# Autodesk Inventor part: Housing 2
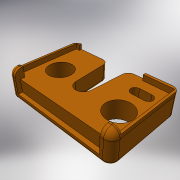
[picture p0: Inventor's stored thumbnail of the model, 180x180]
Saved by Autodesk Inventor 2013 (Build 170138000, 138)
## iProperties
Shininess: 64.0
Length Units: 11269
Angle Units: 11279
Time Units: 11290
Mass Units: 11283
Length Display Precision: 3
Angle Display Precision: 2
Compacted: True
Part Number: Housing 2
Document SubType Name: Modeling
Created: 2005-02
Material: ABS Plastic
Designer: =<Author>
Manufacturer: Standard
Standards Organization: Custom
Density: 1.06 g/cm^3
Description: =<Part Number>
Mass: 41.8001 g
Surface Area: 131.422 cm^2
Volume: 39.4341 cm^3
Density: 0.0
Volumn: 0.0
Area: 0.0
PropertySet Name: Model Information
Control State: 0
Master: False
Checked Out: False
Checked Out Date: 2008-10-15
Last Check In Date: 2008-10-15
d0: 53.000 mm
d1: 79.000 mm
d2: 20.000 mm
d3: 0.00 deg
d4: 2.000 mm
d5: 52.000 mm
d6: 5.000 mm
d11: 7.000 mm
d12: 6.000 mm
d13: 2.000 mm
d14: 2.000 mm
d15: 6.000 mm
d16: 7.000 mm
d17: 2.000 mm
d18: 2.000 mm
d19: 7.000 mm
d20: 0.00 deg
d21: 5.000 mm
d22: 3.000 mm
d23: 0.00 deg
d24: 13.000 mm
d25: 3.000 mm
d26: 0.00 deg
d28: 0.00 deg
d29: 15.000 mm
d30: 40.000 mm
d31: 7.000 mm
d32: 7.000 mm
d34: 0.00 deg
d35: 2.000 mm
d36: 5.000 mm
Author: PVitaliy
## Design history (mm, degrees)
sketch "Эскиз1"
  geometry: L1 (0, 0)-(79, 0); L2 (79, 0)-(79, 53); L3 (79, 53)-(0, 53); L4 (0, 53)-(0, 0)
  constraints: 8 end point, 2 parallel, 1 horizontal, 1 perpendicular, 1 other
  dimensions: "d0" = 53 distance of L3.end L1.start; "d1" = 79 distance of L1.start L1.end
extrude "Выдавливание1" new body sketch "Эскиз1" distance "d2" = 20; taper "d3" = 0 deg
sketch "Эскиз2"
  geometry: L1 (0, 0)-(0, 53) reference; L2 (79, 0)-(0, 0) reference; L3 (79, 53)-(79, 0) reference; L4 (0, 53)-(79, 53) reference; L5 (72, 2)-(7, 2); L6 (2, 6)-(2, 51); L7 (77, 51)-(77, 6); L8 (57, 51)-(57, 53); L9 (5, 51)-(5, 53); L10 (7, 2)-(7, 6); L11 (7, 6)-(2, 6); L12 (77, 6)-(72, 6); L13 (72, 6)-(72, 2); L14 (2, 51)-(5, 51); L15 (57, 51)-(77, 51)
  constraints: 22 end point, 3 perpendicular, 2 collinear, 2 parallel, 2 point on line
  dimensions: "d4" = 2 distance between parallel lines of L3 L7; "d5" = 52 distance between parallel lines of L9 L8; "d6" = 5 distance between parallel lines of L1 L9; "d11" = 7 distance between parallel lines of L10 L1; "d12" = 6 distance between parallel lines of L2 L11; "d13" = 2 distance between parallel lines of L1 L6; "d14" = 2 distance between parallel lines of L2 L5; "d15" = 6 distance between parallel lines of L2 L12; "d16" = 7 distance between parallel lines of L3 L13; "d18" = 2 distance between parallel lines of L15 L4
extrude "Выдавливание2" cut sketch "Эскиз2" distance "d19" = 7; taper "d20" = 0 deg
fillet "Сопряжение1" dims "d21" = 5
sketch "Эскиз3"
  geometry: L1 (57, 53)-(74, 53) reference; L2 (57, 53)-(57, 51) reference; L3 (57, 51)-(77, 51) reference; L4 (77, 51)-(77, 6) reference; L5 (72, 2)-(7, 2) reference; L6 (2, 6)-(2, 51) reference; L7 (2, 51)-(5, 51) reference; L8 (5, 51)-(5, 53) reference; L9 (0, 5)-(0, 48) reference; L10 (74, 0)-(5, 0) reference; L11 (79, 48)-(79, 5) reference; L12 (2, 6)-(0, 6); L13 (7, 2)-(7, 0); L14 (72, 2)-(72, 0); L15 (77, 6)-(79, 6); A1 r 5 centre (74, 48) between (79, 48) and (74, 53) reference; A2 r 5 centre (5, 48) between (5, 53) and (0, 48) reference
  constraints: 8 end point, 4 perpendicular, 4 point on line
extrude "Выдавливание3" cut sketch "Эскиз3" distance "d22" = 3; taper "d23" = 0 deg
sketch "Эскиз4"
  geometry: L1 (67, 17)-(2, 17) reference; L2 (0, 0)-(69, 0) reference; L3 (69, 20)-(67, 20) reference; L4 (2, 17)-(2, 4); L5 (2, 4)-(67, 4); L6 (67, 4)-(67, 17)
  constraints: 6 end point, 2 perpendicular, 1 parallel
  dimensions: "d24" = 13 distance between parallel lines of L5 L1
extrude "Выдавливание4" cut sketch "Эскиз4" distance "d25" = 3; taper "d26" = 0 deg
sketch "Эскиз5"
  geometry: L1 (-74, 53)-(-5, 53) reference; L2 (-31.014, 23.587)-(-29.307, 48.344) reference; L3 (-44.669, 48.339)-(-42.986, 23.593) reference; C1 r 9 at (-15, 26) reference; C2 r 9 at (-65, 21) reference; A1 r 6 centre (-37, 24) between (-42.986, 23.593) and (-31.014, 23.587) reference; A2 r 5 centre (-24.319, 48) between (-24.319, 53) and (-29.307, 48.344) reference; A3 r 5 centre (-49.658, 48) between (-44.669, 48.339) and (-49.658, 53) reference
extrude "Выдавливание5" cut sketch "Эскиз5" stored distance "d27" = 3; taper "d28" = 0 deg
sketch "Эскиз6"
  geometry: L1 (-79, 5)-(-79, 48) reference; L2 (-5, 0)-(-74, 0) reference; L3 (-72, 40)-(-57, 40); L4 (-68.5, 43.5)-(-60.5, 43.5); L5 (-68.5, 36.5)-(-60.5, 36.5); A1 r 3.5 centre (-68.5, 40) between (-68.5, 43.5) and (-68.5, 36.5); A2 r 3.5 centre (-60.5, 40) between (-60.5, 36.5) and (-60.5, 43.5)
  constraints: 6 end point, 6 point on circle, 3 tangent, 2 centre point, 2 point on line, 1 equal radius, 1 horizontal
  dimensions: "d29" = 15 distance of L3.start L3.end; "d30" = 40 distance between parallel lines of L2 L3; "d31" = 7 distance from line of L1 L3.start; "d32" = 7 distance between parallel lines of L5 L4
extrude "Выдавливание6" cut sketch "Эскиз6" stored distance "d33" = 3; taper "d34" = 0 deg
fillet "Сопряжение2" dims "d35" = 2
fillet "Сопряжение3" dims "d36" = 5
body "Solid1"
node "ЗаимстЛин1"
node "ЗаимстЛин2"
node "ЗаимстЛин3"
node "ЗаимстЛин4"
node "ЗаимстЛин5"
node "ЗаимстЛин6"
node "ЗаимстЛин7"
other parameters: "d17" = 2
